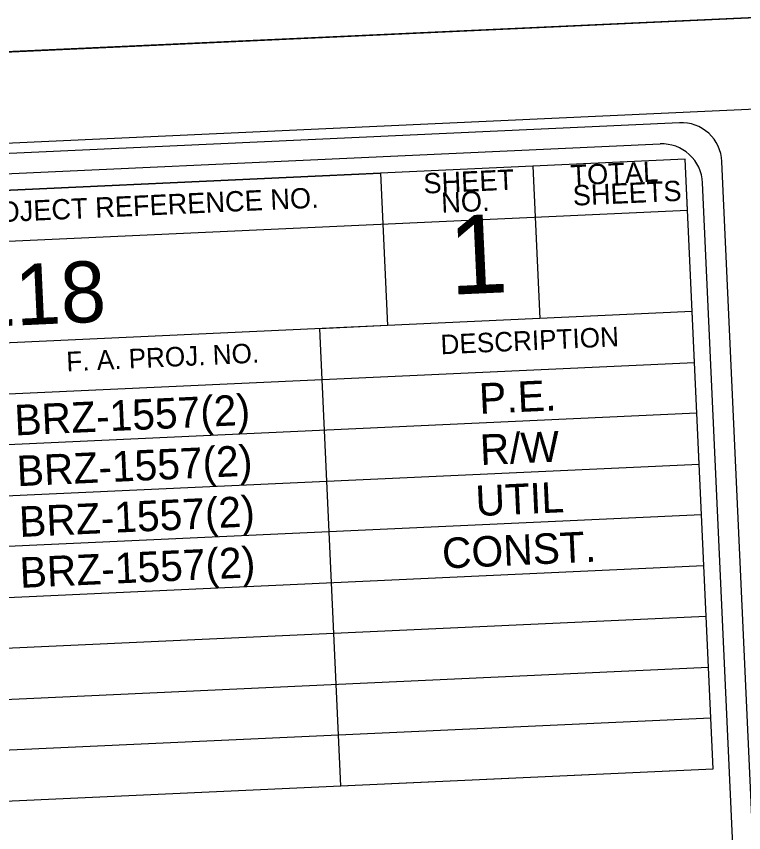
# Model space of a CAD drawing. Extents: x 1190067 to 1192950, y 891516 to 893460.
# Drawn here: x 1191844 to 1191987.1, y 893299 to 893459.6 of the extents above; entities that cross this region are included whole.
import ezdxf

# ---------------------------------------------------------------- set-up
doc = ezdxf.new("R2010")
doc.units = 0
for name, color, linetype in [('Sheet Cutting Line CELL', 7, 'Continuous'), ('Sheet Data Field CELL', 7, 'Continuous'), ('Sheet Plot Border Inside CELL', 7, 'Continuous'), ('Sheet Plot Border Outside CELL', 7, 'Continuous'), ('Sheet Title CELL', 7, 'Continuous')]:
    doc.layers.add(name, color=color, linetype=linetype)

msp = doc.modelspace()

# ---------------------------------------------------------------- linework, layer by layer
at = {"layer": 'Sheet Cutting Line CELL'}
msp.add_line((1190649.32, 893398.03), (1191995.11, 893459.6), dxfattribs=at)
at = {"layer": 'Sheet Plot Border Inside CELL'}
msp.add_lwpolyline([(1190699.11, 892537.37), (1192030.91, 892598.3), (1191992.34, 893441.49), (1190660.53, 893380.56)], close=True, dxfattribs=at)
at = {"layer": 'Sheet Plot Border Outside CELL'}
msp.add_lwpolyline([(1191995.11, 893459.6), (1190649.32, 893398.03), (1190689.54, 892518.96), (1192035.33, 892580.53)], close=True, dxfattribs=at)
at = {"layer": 'Sheet Title CELL'}
for points in [[(1191974.46, 893438.63), (1190791.68, 893384.53)], [(1191970.64, 893434.46), (1190835.83, 893382.54)], [(1191756.26, 893411.44), (1191976.04, 893421.5), (1191975.58, 893431.49), (1191755.81, 893421.42)], [(1191785.78, 893422.8), (1191915.65, 893428.74), (1191917.01, 893398.78), (1191903.67, 893398.17), (1191907.78, 893308.26), (1191981.06, 893311.61), (1191975.58, 893431.49), (1191945.61, 893430.12), (1191946.99, 893400.15)], [(1192020.47, 892607.88), (1191982.81, 893431.01)], [(1192009.52, 892759.53), (1191978.99, 893426.84)], [(1191757.64, 893381.47), (1191977.41, 893391.52), (1191976.95, 893401.52), (1191757.18, 893391.46)], [(1191758.55, 893361.49), (1191978.32, 893371.55), (1191977.86, 893381.53), (1191758.09, 893371.48)], [(1191759.46, 893341.52), (1191979.23, 893351.57), (1191978.78, 893361.56), (1191759.01, 893351.51)], [(1191760.38, 893321.53), (1191980.15, 893331.58), (1191979.69, 893341.57), (1191759.93, 893331.52)], [(1191761.29, 893301.56), (1191981.06, 893311.61), (1191980.61, 893321.59), (1191760.84, 893311.55)]]:
    msp.add_lwpolyline(points, dxfattribs=at)
for centre in [(1191974.82, 893430.69), (1191971, 893426.51)]:
    msp.add_arc(centre, 8, 2.6195, 92.6195, dxfattribs=at)

# ---------------------------------------------------------------- texts
at = {"layer": 'Sheet Data Field CELL'}
for s, height, p in [('B-5118    ', 12, (1191810.2, 893397.24)), ('P.E.', 6, (1191935.18, 893381.42)), ('BRZ-1557(2)   ', 6, (1191843.8, 893377.16)), ('R/W', 6, (1191935.36, 893371.34)), ('BRZ-1557(2)   ', 6, (1191844.26, 893367.17)), ('UTIL', 6, (1191934.49, 893361.29)), ('BRZ-1557(2)   ', 6, (1191844.72, 893357.19)), ('CONST.', 6, (1191927.9, 893350.98)), ('BRZ-1557(2)   ', 6, (1191844.83, 893347.18))]:
    msp.add_text(s, height=height, rotation=2.6195, dxfattribs=at).set_placement(p)
at = {"layer": 'Sheet Title CELL'}
for s, height, p in [('TOTAL', 4, (1191953.11, 893426.34)), ('SHEET', 4, (1191924.19, 893424.72)), ('SHEETS', 4, (1191953.56, 893422.35)), ('STATE PROJECT REFERENCE NO.', 3.9998, (1191814.51, 893417.9)), ('NO.', 4, (1191927.69, 893420.93)), ('1', 15.48, (1191929.43, 893404.83)), ('DESCRIPTION', 3.84, (1191927.56, 893393.12)), ('F. A. PROJ. NO.', 3.84, (1191853.96, 893389.77))]:
    msp.add_text(s, height=height, rotation=2.6195, dxfattribs=at).set_placement(p)

doc.saveas('drawing.dxf')
